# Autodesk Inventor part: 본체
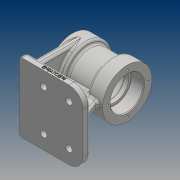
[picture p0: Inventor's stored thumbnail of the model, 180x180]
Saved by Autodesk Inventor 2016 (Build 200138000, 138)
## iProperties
Created: 2020-06
Part Number: 본체
Material: 일반
Document SubType Name: Modeling
Designer: 605-17
Density: 1 g/cm^3
Appearance: 기본값
Author: 605-17
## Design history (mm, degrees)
sketch "스케치1"
  geometry: L1 (-45, 0)-(45, 0); L2 (45, 0)-(45, 10); L3 (45, 10)-(-45, 10); L4 (-45, 10)-(-45, 0); 2 further points
  constraints: 8 end point, 2 perpendicular, 1 coincident, 1 horizontal, 1 midpoint, 1 parallel
  dimensions: "d0" = 90 distance of L1.start L1.end; "d1" = 10 distance of L1.end L2.end
extrude "돌출1" new body sketch "스케치1" stored distance "d2" = 98; taper "d3" = 0 deg
sketch "스케치2"
  geometry: L1 (-50, 80)-(28, 80); L2 (-45, 10)-(-45, 0) reference; L3 (-45, 0)-(45, 0) reference; L4 (-50, 115)-(-28, 115); L5 (6, 115)-(28, 115); L6 (28, 115)-(28, 103.5); L7 (28, 103.5)-(10, 103.5); L8 (10, 103.5)-(10, 100); L9 (10, 100)-(4, 100); L10 (4, 100)-(4, 103); L11 (4, 103)-(-26, 103); L12 (-26, 103)-(-26, 100); L13 (-26, 100)-(-32, 100); L14 (-32, 100)-(-32, 103.5); L15 (-32, 103.5)-(-50, 103.5); L16 (-50, 103.5)-(-50, 115); L17 (-28, 115)-(-28, 109); L18 (-28, 109)-(6, 109); L19 (-5, 109)-(6, 109); L20 (6, 109)-(6, 115); 1 further point
  constraints: 36 end point, 12 perpendicular, 4 horizontal alignment, 2 horizontal, 2 vertical alignment, 1 vertical
  dimensions: "d4" = 78 distance of L1.start L1.end; "d5" = 5 distance from line of L2 L1.start; "d6" = 80 distance between parallel lines of L1 L3; "d7" = 46 diameter of L11 L1; "d8" = 40 diameter of L9 L1; "d9" = 18 distance of L14.end L15.end; "d10" = 6 distance of L12.end L13.end; "d11" = 30 distance of L10.end L11.end; "d12" = 6 distance of L8.end L9.end; "d13" = 47 diameter of L7 L1; "d14" = 70 diameter of L4 L1; "d15" = 22 distance of L4.start L4.end; "d17" = 70 diameter of L5 L1; "d62" = 58 diameter of L18 L1; "d63" = 22 distance between parallel lines of L6 L20
revolve "회전1" sketch "스케치2" stored, may be unused: angle "d24" = 90 deg
sketch "스케치3"
  geometry: L1 (10, 84)-(10, 14); L2 (10, 84)-(0, 84); L3 (0, 0)-(0, 98) reference; L4 (10, 14)-(0, 14); 2 further points
  constraints: 6 end point, 2 horizontal, 2 point on line, 1 horizontal alignment, 1 midpoint, 1 vertical
  dimensions: "d25" = 70 distance of L1.start L1.end; "d26" = 10 distance of L1.start L2.end
extrude "돌출2" join sketch "스케치3" stored distance "d27" = 98; taper "d28" = 0 deg
sketch "스케치4"
  geometry: L1 (-45, 10)-(45, 10) reference; L2 (33, 10)-(25.126, 31.633); L3 (45, 0)-(45, 10) reference; 1 further point
  constraints: 2 end point, 1 point on line
  dimensions: "d29" = 12 distance from line of L2.start L3; "d30" = 70 deg angle of L2 L1
feature "리브1" sketch "스케치4" dims "d31" = 1, "d32" = 10, "d33" = 0, "d34" = 0, "d35" = 1, "d36" = 1
sketch "스케치5"
  geometry: L1 (0, 0)-(0, 98) reference; L2 (70, 20)-(34, 20); L3 (34, 20)-(34, 78); L4 (34, 78)-(70, 78); L5 (70, 78)-(70, 20); L6 (70, 20)-(34, 78); L7 (34, 20)-(70, 78); 3 further points
  constraints: 12 end point, 3 midpoint, 2 parallel, 1 horizontal, 1 horizontal alignment, 1 perpendicular
  dimensions: "d91" = 36 distance of L3.end L4.end; "d92" = 70 distance between parallel lines of L5 L1; "d93" = 58 distance of L4.end L2.start
hole "구멍1" sketch "스케치5" at (70, 20), (34, 20), (70, 78), (34, 78) diameter "d39" = 9; stored, may be unused: countersink angle "d43" = 90 deg, drill point angle "d45" = 118 deg; dims "d40" = 6, "d41" = 4, "d42" = 2, "d44" = 8
sketch "스케치6"
  geometry: L1 (0, -28.5)-(0, 28.5); L2 (-28.5, 0)-(28.5, 0); C1 r 23.5 at (0, 0) reference; A1 r 28.5 centre (0, 0) between (0, 28.5) and (0, -28.5); 1 further point
  constraints: 4 end point, 4 point on circle, 2 midpoint, 1 centre point, 1 coincident, 1 horizontal, 1 vertical
  dimensions: "d46" = 28.5 radius of A1
hole "구멍2" sketch "스케치6" at (0, 28.5), (28.5, 0), (0, -28.5), (-28.5, 0) diameter "d47" = 3.242; stored, may be unused: countersink angle "d51" = 90 deg, drill point angle "d53" = 118 deg; dims "d48" = 10, "d49" = 4, "d50" = 2, "d52" = 12
sketch "스케치7"
  geometry: L1 (0, -28.5)-(0, 28.5); L2 (-28.5, 0)-(28.5, 0); C1 r 20 at (0, 0) reference; C2 r 1.621 at (0, 28.5) reference; A1 r 28.5 centre (0, 0) between (0, -28.5) and (28.5, 0); 1 further point
  constraints: 4 end point, 3 point on circle, 2 midpoint, 1 centre point, 1 coincident, 1 horizontal, 1 vertical
  dimensions: "d54" = 28.5 radius of A1
hole "구멍3" sketch "스케치7" at (28.5, 0), (0, 28.5), (-28.5, 0), (0, -28.5) diameter "d55" = 3.242; stored, may be unused: countersink angle "d59" = 90 deg, drill point angle "d61" = 118 deg; dims "d56" = 10, "d57" = 4, "d58" = 2, "d60" = 12
node "작업 평면1"
sketch "스케치8"
  geometry: L1 (-5, 14)-(-5, 84) reference; C1 r 6 at (34, 49); 1 further point
  constraints: 1 centre point, 1 horizontal alignment
  dimensions: "d65" = 39 distance from line of C1.centre L1; "d66" = 12 diameter of C1
extrude "돌출3" join sketch "스케치8" stored distance "d67" = 98; taper "d68" = 0 deg
hole "구멍4" diameter "d71" = 5.188; stored, may be unused: countersink angle "d75" = 90 deg, drill point angle "d77" = 118 deg; dims "d69" = 10, "d70" = 10, "d72" = 12, "d73" = 4, "d74" = 2, "d76" = 16
fillet "모깎기1" dims "d78" = 20, "d79" = 3, "d88" = 0.3
fillet "모깎기2" dims "d80" = 3
chamfer "모따기1" distance "d81" = 1; stored, may be unused: second distance "d82" = 2, angle "d83" = 45 deg
sketch "스케치9"
  geometry: L1 (-27.976, 6.402)-(27.976, 6.402); L2 (27.976, 6.402)-(27.976, 1.598); L3 (27.976, 1.598)-(-27.976, 1.598); L4 (-27.976, 1.598)-(-27.976, 6.402); L5 (-27.976, 4)-(27.976, 4); L6 (0, 6.402)-(0, 1.598); L7 (-45, 0)-(25, 0) reference; L8 (-45, 7)-(-45, 0) reference; 1 further point
  constraints: 4 end point, 4 midpoint, 2 other
  dimensions: "d84" = 4 distance between parallel lines of L5 L7; "d85" = 45 distance between parallel lines of L6 L8
feature "엠보싱1" sketch "스케치9" dims "d7" = 46, "d86" = 0.5, "d87" = 0
fillet "모깎기3" dims "d94" = 3
node "솔리드1"
other parameters: "d64" = -112
